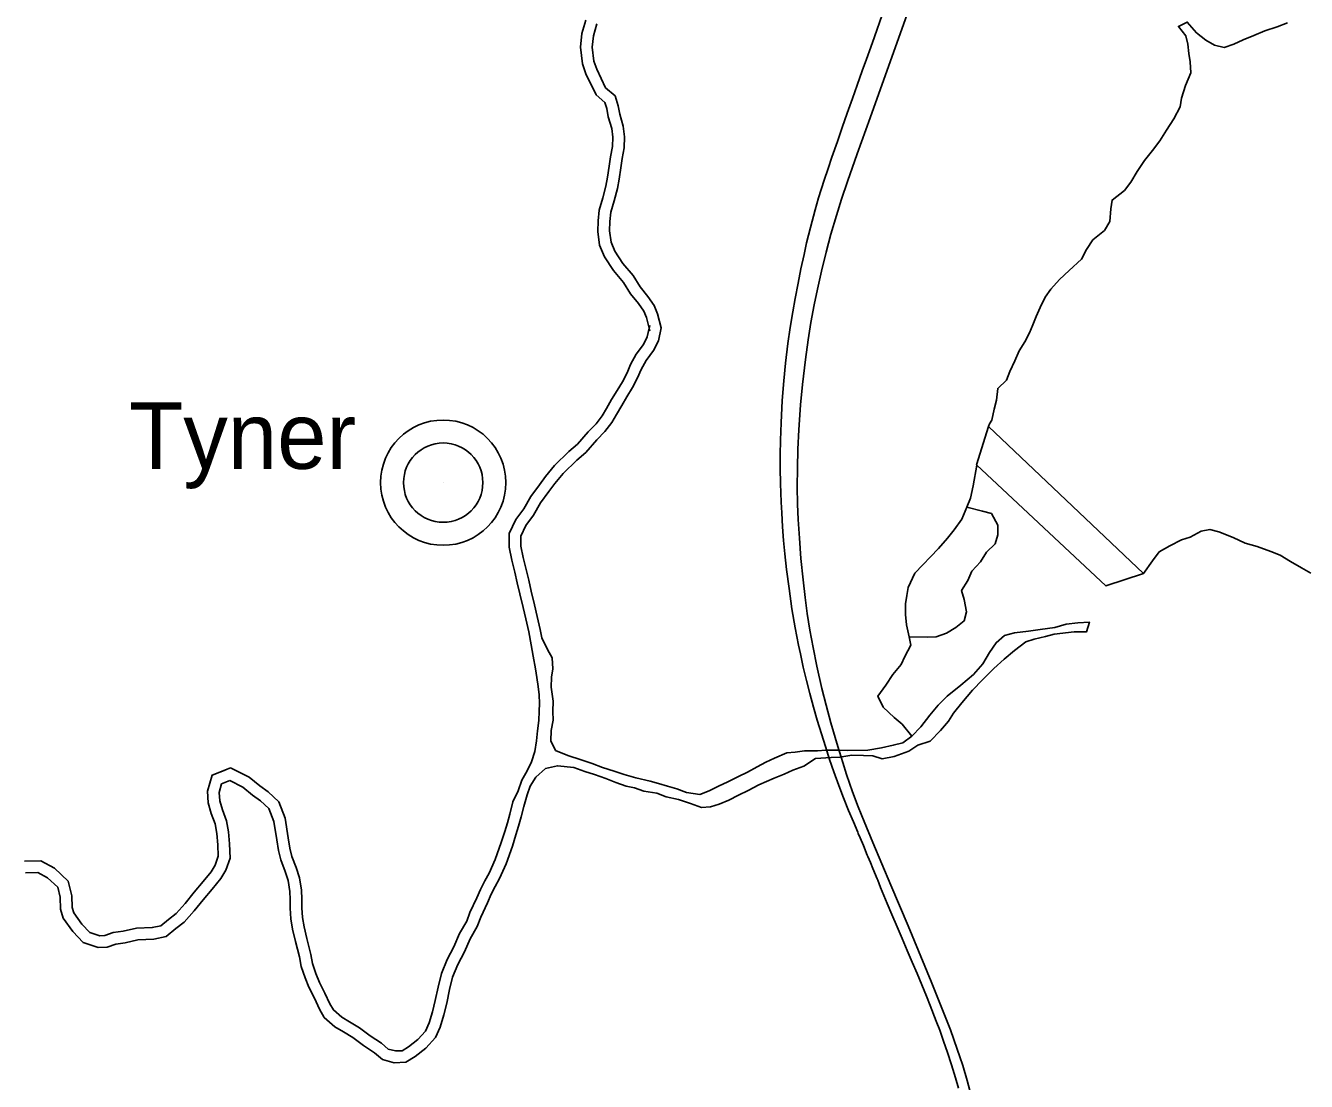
# Model space of a CAD drawing. Extents: x -12.1 to 34, y 0 to 22.
# Drawn here: x 8.417 to 9.844, y 14.694 to 15.871 of the extents above; entities that cross this region are included whole.
import ezdxf

# ---------------------------------------------------------------- set-up
doc = ezdxf.new("R2010")
doc.units = 0
for name, color, linetype in [('GM_X_Interstate_Route', 7, 'Continuous'), ('GM_X_Major_Lake', 7, 'Continuous'), ('GM_X_Major_River', 7, 'Continuous'), ('GM_X_Unincorporated', 7, 'Continuous'), ('GM_X_Unincorporated_Location', 7, 'Continuous'), ('GM_X_Unincorporated_Text', 7, 'Continuous')]:
    doc.layers.add(name, color=color, linetype=linetype)

msp = doc.modelspace()

# ---------------------------------------------------------------- linework, layer by layer
at = {"layer": 'GM_X_Interstate_Route'}
for points in [[(9.4582, 14.7214), (9.4553, 14.73), (9.4476, 14.7514), (9.4382, 14.7758), (9.4262, 14.8055), (9.4005, 14.8673), (9.3812, 14.9129), (9.3613, 14.9605), (9.3515, 14.9838), (9.345, 15), (9.3387, 15.0169), (9.3319, 15.0362), (9.3276, 15.0495), (9.3221, 15.0673), (9.3145, 15.0937), (9.3092, 15.1133), (9.3045, 15.132), (9.2989, 15.157), (9.2947, 15.1776), (9.2911, 15.1971), (9.2881, 15.2155), (9.2857, 15.2334), (9.2834, 15.2531), (9.2811, 15.2769), (9.2793, 15.2996), (9.2781, 15.3205), (9.2774, 15.3374), (9.277, 15.3567), (9.2771, 15.3776), (9.2776, 15.3986), (9.2786, 15.4202), (9.2806, 15.4481), (9.2827, 15.4707), (9.286, 15.4985), (9.289, 15.5205), (9.2922, 15.54), (9.2957, 15.5595), (9.2994, 15.5772), (9.3039, 15.5971), (9.3091, 15.6181), (9.3145, 15.6383), (9.3206, 15.659), (9.3264, 15.6774), (9.3331, 15.6972), (9.3439, 15.728), (9.3581, 15.7681), (9.4368, 15.9891)], [(9.4566, 14.6867), (9.4533, 14.6979), (9.4489, 14.7124), (9.4444, 14.7263), (9.4401, 14.739), (9.4358, 14.7511), (9.4319, 14.7614), (9.4252, 14.7788), (9.421, 14.7891), (9.4156, 14.8019), (9.4104, 14.8143), (9.4049, 14.8271), (9.3996, 14.84), (9.3939, 14.8534), (9.3884, 14.8663), (9.3825, 14.8802), (9.3773, 14.8925), (9.3717, 14.9059), (9.3699, 14.9102), (9.3666, 14.9183), (9.366, 14.9199), (9.3612, 14.9312), (9.3584, 14.9382), (9.3557, 14.9446), (9.3553, 14.9456), (9.355, 14.9462), (9.3506, 14.957), (9.347, 14.9656), (9.345, 14.9704), (9.3443, 14.972), (9.3395, 14.9833), (9.3342, 14.9962), (9.3285, 15.0102), (9.3232, 15.0237), (9.3177, 15.039), (9.313, 15.0528), (9.3083, 15.0672), (9.3038, 15.0816), (9.2992, 15.0967), (9.295, 15.1112), (9.2908, 15.1264), (9.2871, 15.141), (9.2836, 15.1557), (9.2804, 15.1705), (9.2784, 15.1802), (9.2747, 15.1996), (9.271, 15.2209), (9.2678, 15.2433), (9.2651, 15.2647), (9.2632, 15.2821), (9.2618, 15.2971), (9.2606, 15.3122), (9.2596, 15.3279), (9.2589, 15.3395), (9.2581, 15.3604), (9.2578, 15.3773), (9.2579, 15.3924), (9.2581, 15.4087), (9.2589, 15.4279), (9.2603, 15.4529), (9.262, 15.475), (9.2639, 15.4946), (9.2666, 15.5166), (9.2692, 15.5345), (9.272, 15.5517), (9.2746, 15.5666), (9.2778, 15.5838), (9.281, 15.5997), (9.2845, 15.6157), (9.2874, 15.6287), (9.2916, 15.6457), (9.2968, 15.6654), (9.3007, 15.6788), (9.307, 15.6987), (9.3113, 15.7114), (9.3156, 15.7241), (9.3217, 15.7417), (9.3271, 15.7571), (9.3326, 15.7731), (9.3384, 15.7896), (9.3437, 15.8044), (9.3494, 15.8203), (9.3541, 15.8334), (9.3588, 15.8466), (9.3629, 15.8581), (9.3717, 15.8828)], [(9.4709, 14.6783), (9.4663, 14.6951), (9.4613, 14.7118), (9.4582, 14.7214)]]:
    msp.add_lwpolyline(points, dxfattribs=at)
at = {"layer": 'GM_X_Major_Lake'}
msp.add_line((9.4899, 15.4241), (9.6629, 15.2602), dxfattribs=at)
for points in [[(9.8232, 15.8739), (9.8118, 15.8696), (9.7981, 15.8648), (9.7857, 15.8598), (9.774, 15.8551), (9.7634, 15.85), (9.7528, 15.8464), (9.7418, 15.8491), (9.7322, 15.8547), (9.7219, 15.8628), (9.7115, 15.8748), (9.7017, 15.8698), (9.7099, 15.8595), (9.7121, 15.85), (9.7135, 15.8397), (9.7147, 15.8304), (9.7155, 15.818), (9.7095, 15.8041), (9.705, 15.7899), (9.7037, 15.7803), (9.6967, 15.7667), (9.6883, 15.7542), (9.6809, 15.7424), (9.6728, 15.7317), (9.664, 15.7206), (9.6556, 15.7081), (9.6486, 15.6964), (9.6416, 15.6871), (9.6278, 15.6763), (9.6265, 15.6667), (9.6252, 15.6525), (9.6192, 15.6425), (9.6065, 15.6321), (9.5992, 15.6214), (9.5936, 15.6103), (9.5798, 15.5978), (9.5693, 15.5878), (9.5594, 15.577), (9.5531, 15.5681), (9.5475, 15.5567), (9.5433, 15.5467), (9.5395, 15.5374), (9.5357, 15.5285), (9.5304, 15.5185), (9.5244, 15.5082), (9.5196, 15.4971), (9.514, 15.4854), (9.5101, 15.4757), (9.5003, 15.4664), (9.499, 15.4533), (9.4965, 15.4433), (9.4938, 15.4309), (9.4913, 15.4269), (9.4899, 15.4241)], [(9.6629, 15.2602), (9.4899, 15.4241), (9.4913, 15.4269), (9.4938, 15.4309), (9.4965, 15.4433), (9.499, 15.4533), (9.5003, 15.4664), (9.5101, 15.4757), (9.514, 15.4854), (9.5196, 15.4971), (9.5244, 15.5082), (9.5304, 15.5185), (9.5357, 15.5285), (9.5395, 15.5374), (9.5433, 15.5467), (9.5475, 15.5567), (9.5531, 15.5681), (9.5594, 15.577), (9.5693, 15.5878), (9.5798, 15.5978), (9.5936, 15.6103), (9.5992, 15.6214), (9.6065, 15.6321), (9.6192, 15.6425), (9.6252, 15.6525), (9.6265, 15.6667), (9.6278, 15.6763), (9.6416, 15.6871), (9.6486, 15.6964), (9.6556, 15.7081), (9.664, 15.7206), (9.6728, 15.7317), (9.6809, 15.7424), (9.6883, 15.7542), (9.6967, 15.7667), (9.7037, 15.7803), (9.705, 15.7899), (9.7095, 15.8041), (9.7155, 15.818), (9.7147, 15.8304), (9.7135, 15.8397), (9.7121, 15.85), (9.7099, 15.8595), (9.7017, 15.8698), (9.7115, 15.8748), (9.7219, 15.8628), (9.7322, 15.8547), (9.7418, 15.8491), (9.7528, 15.8464), (9.7634, 15.85), (9.774, 15.8551), (9.7857, 15.8598), (9.7981, 15.8648), (9.8118, 15.8696), (9.8232, 15.8739)], [(9.6629, 15.2602), (9.6727, 15.2741), (9.6801, 15.2842), (9.6921, 15.291), (9.7051, 15.2975), (9.7147, 15.3008), (9.727, 15.3072), (9.7366, 15.3091), (9.7469, 15.3067), (9.7629, 15.3001), (9.776, 15.2938), (9.7895, 15.2903), (9.8048, 15.2847), (9.8151, 15.2806), (9.8265, 15.2735), (9.8389, 15.2665), (9.8492, 15.2606)]]:
    msp.add_lwpolyline(points, dxfattribs=at)
at = {"layer": 'GM_X_Major_River'}
for p, q in [((9.4899, 15.4241), (9.4768, 15.3813)), ((9.6629, 15.2602), (9.4899, 15.4241)), ((9.4768, 15.3813), (9.6208, 15.2464)), ((9.6208, 15.2464), (9.6629, 15.2602))]:
    msp.add_line(p, q, dxfattribs=at)
for points in [[(9.1127, 15.5306), (9.1089, 15.5453), (9.1058, 15.5527), (9.1001, 15.5611), (9.0913, 15.5719), (9.0835, 15.5845), (9.0722, 15.5978), (9.0622, 15.6132), (9.0567, 15.6259), (9.0548, 15.6415), (9.0552, 15.6532), (9.0563, 15.6652), (9.0604, 15.679), (9.0637, 15.6919), (9.0656, 15.7018), (9.0673, 15.7141), (9.069, 15.7246), (9.071, 15.736), (9.0715, 15.7465), (9.0703, 15.756), (9.0664, 15.7691), (9.0646, 15.7783), (9.0626, 15.785), (9.0527, 15.7935), (9.0415, 15.8171), (9.0376, 15.8283), (9.0353, 15.8468), (9.037, 15.8618), (9.0412, 15.877)], [(9.0412, 15.877), (9.037, 15.8618), (9.0353, 15.8468), (9.0376, 15.8283), (9.0415, 15.8171), (9.0527, 15.7935), (9.0626, 15.785), (9.0646, 15.7783), (9.0664, 15.7691), (9.0703, 15.756), (9.0715, 15.7465), (9.071, 15.736), (9.069, 15.7246), (9.0673, 15.7141), (9.0656, 15.7018), (9.0637, 15.6919), (9.0604, 15.679), (9.0563, 15.6652), (9.0552, 15.6532), (9.0548, 15.6415), (9.0567, 15.6259), (9.0622, 15.6132), (9.0722, 15.5978), (9.0835, 15.5845), (9.0913, 15.5719), (9.1001, 15.5611), (9.1058, 15.5527), (9.1089, 15.5453), (9.1119, 15.5336)], [(9.1253, 15.5338), (9.1213, 15.5494), (9.1174, 15.559), (9.1106, 15.5689), (9.102, 15.5795), (9.0941, 15.5922), (9.0827, 15.6056), (9.0737, 15.6194), (9.0694, 15.6293), (9.0679, 15.6421), (9.0682, 15.6524), (9.0692, 15.6627), (9.073, 15.6755), (9.0765, 15.6891), (9.0785, 15.6997), (9.0802, 15.7122), (9.0819, 15.7225), (9.084, 15.7346), (9.0846, 15.747), (9.0831, 15.7587), (9.0791, 15.7722), (9.0773, 15.7814), (9.074, 15.7924), (9.0633, 15.8016), (9.0536, 15.8221), (9.0504, 15.8313), (9.0485, 15.8469), (9.0498, 15.8594), (9.0536, 15.8729)], [(9.1119, 15.5336), (9.1098, 15.524), (9.1055, 15.5154), (9.0976, 15.5045), (9.0912, 15.4932), (9.0873, 15.4838), (9.0822, 15.4739), (9.0761, 15.464), (9.07, 15.4542), (9.0644, 15.4441), (9.0595, 15.4359), (9.0528, 15.4268), (9.044, 15.4179), (9.032, 15.4043), (9.0225, 15.396), (9.0066, 15.3806), (8.9965, 15.3684), (8.9896, 15.3591), (8.98, 15.3459), (8.9723, 15.3324), (8.9632, 15.3203), (8.9558, 15.3046), (8.9559, 15.2894), (8.9588, 15.2751), (8.9621, 15.2617), (8.965, 15.2498), (8.9679, 15.2374), (8.9716, 15.2222), (8.9745, 15.2095), (8.9777, 15.1951), (8.9806, 15.1805), (8.9828, 15.1679), (8.9853, 15.1538), (8.9868, 15.1441), (8.9882, 15.1344), (8.9893, 15.1248), (8.9897, 15.1151), (8.9894, 15.1069), (8.9888, 15.0964), (8.9875, 15.0848), (8.9865, 15.0738), (8.9844, 15.0617), (8.9807, 15.0502), (8.9761, 15.0404), (8.9702, 15.0299), (8.9658, 15.0181), (8.96, 15.0057), (8.9566, 14.992), (8.9539, 14.9822), (8.9509, 14.9728), (8.9471, 14.9604), (8.9404, 14.9413), (8.9335, 14.9263), (8.9288, 14.9176), (8.9239, 14.908), (8.92, 14.8986), (8.9122, 14.8824), (8.9086, 14.8725), (8.9007, 14.8589), (8.8943, 14.844), (8.8869, 14.8301), (8.8804, 14.8143), (8.8766, 14.7992), (8.8735, 14.7842), (8.8706, 14.7717), (8.8668, 14.7593), (8.8627, 14.7501), (8.8543, 14.7407), (8.8438, 14.7326), (8.8368, 14.7283), (8.8294, 14.728), (8.821, 14.7302), (8.8137, 14.7366), (8.8009, 14.7449), (8.789, 14.7538), (8.778, 14.7605), (8.7694, 14.7656), (8.76, 14.7738), (8.7562, 14.7806), (8.7506, 14.7924), (8.7447, 14.8045), (8.7406, 14.8143), (8.7368, 14.8254), (8.735, 14.8355), (8.7305, 14.8533), (8.7274, 14.8662), (8.7257, 14.8768), (8.725, 14.8875), (8.7249, 14.8973), (8.7245, 14.9072), (8.7224, 14.9209), (8.7187, 14.9326), (8.7138, 14.9449), (8.7116, 14.9541), (8.7098, 14.9654), (8.7063, 14.9873), (8.6993, 15.0055), (8.6872, 15.017), (8.6779, 15.0236), (8.6661, 15.033), (8.6455, 15.0437)], [(8.6507, 15.0409), (8.6661, 15.033), (8.6779, 15.0236), (8.6872, 15.017), (8.6993, 15.0055), (8.7063, 14.9873), (8.7098, 14.9654), (8.7116, 14.9541), (8.7138, 14.9449), (8.7187, 14.9326), (8.7224, 14.9209), (8.7245, 14.9072), (8.7249, 14.8973), (8.725, 14.8875), (8.7257, 14.8768), (8.7274, 14.8662), (8.7305, 14.8533), (8.735, 14.8355), (8.7368, 14.8254), (8.7406, 14.8143), (8.7447, 14.8045), (8.7506, 14.7924), (8.7562, 14.7806), (8.76, 14.7738), (8.7694, 14.7656), (8.778, 14.7605), (8.789, 14.7538), (8.8009, 14.7449), (8.8137, 14.7366), (8.821, 14.7302), (8.8294, 14.728), (8.8368, 14.7283), (8.8438, 14.7326), (8.8543, 14.7407), (8.8627, 14.7501), (8.8668, 14.7593), (8.8706, 14.7717), (8.8735, 14.7842), (8.8766, 14.7992), (8.8804, 14.8143), (8.8869, 14.8301), (8.8943, 14.844), (8.9007, 14.8589), (8.9086, 14.8725), (8.9122, 14.8824), (8.92, 14.8986), (8.9239, 14.908), (8.9288, 14.9176), (8.9335, 14.9263), (8.9404, 14.9413), (8.9471, 14.9604), (8.9509, 14.9728), (8.9539, 14.9822), (8.9566, 14.992), (8.96, 15.0057), (8.9658, 15.0181), (8.9702, 15.0299), (8.9761, 15.0404), (8.9807, 15.0502), (8.9844, 15.0617), (8.9865, 15.0738), (8.9875, 15.0848), (8.9888, 15.0964), (8.9894, 15.1069), (8.9897, 15.1151), (8.9893, 15.1248), (8.9882, 15.1344), (8.9868, 15.1441), (8.9853, 15.1538), (8.9828, 15.1679), (8.9806, 15.1805), (8.9777, 15.1951), (8.9745, 15.2095), (8.9716, 15.2222), (8.9679, 15.2374), (8.965, 15.2498), (8.9621, 15.2617), (8.9588, 15.2751), (8.9559, 15.2894), (8.9558, 15.3046), (8.9632, 15.3203), (8.9723, 15.3324), (8.98, 15.3459), (8.9896, 15.3591), (8.9965, 15.3684), (9.0066, 15.3806), (9.0225, 15.396), (9.032, 15.4043), (9.044, 15.4179), (9.0528, 15.4268), (9.0595, 15.4359), (9.0644, 15.4441), (9.07, 15.4542), (9.0761, 15.464), (9.0822, 15.4739), (9.0873, 15.4838), (9.0912, 15.4932), (9.0976, 15.5045), (9.1055, 15.5154), (9.1098, 15.524), (9.1126, 15.5366)], [(8.9923, 15.1886), (8.9905, 15.1978), (8.9872, 15.2124), (8.9843, 15.2251), (8.9806, 15.2404), (8.9777, 15.2528), (8.9748, 15.2648), (8.9715, 15.278), (8.9689, 15.2907), (8.9689, 15.3017), (8.9745, 15.3135), (8.9832, 15.3253), (8.9909, 15.3389), (9.0001, 15.3514), (9.0067, 15.3603), (9.0162, 15.3717), (9.0314, 15.3864), (9.0412, 15.395), (9.0535, 15.409), (9.0627, 15.4183), (9.0704, 15.4286), (9.0757, 15.4375), (9.0813, 15.4475), (9.0872, 15.4572), (9.0935, 15.4675), (9.0991, 15.4782), (9.103, 15.4875), (9.1086, 15.4975), (9.1167, 15.5086), (9.1222, 15.5196), (9.1253, 15.5338)], [(9.4899, 15.4241), (9.6629, 15.2602), (9.6208, 15.2464), (9.4768, 15.3813), (9.4899, 15.4241)], [(9.4772, 15.381), (9.473, 15.3579), (9.4699, 15.3443), (9.4661, 15.334), (9.4605, 15.3208), (9.4517, 15.3087), (9.4444, 15.2994), (9.4345, 15.2879), (9.4078, 15.2607), (9.4004, 15.2447), (9.3991, 15.2358), (9.3977, 15.2265), (9.3975, 15.2145), (9.3986, 15.2031), (9.4015, 15.1896), (9.4037, 15.1804), (9.3967, 15.1676), (9.3929, 15.1587), (9.3834, 15.1476), (9.3757, 15.1358), (9.3669, 15.1236), (9.3726, 15.1113), (9.3848, 15.0996), (9.394, 15.0922), (9.4047, 15.0788)], [(9.4661, 15.334), (9.4605, 15.3208), (9.4517, 15.3087), (9.4444, 15.2994), (9.4345, 15.2879), (9.4078, 15.2607), (9.4004, 15.2447), (9.3991, 15.2358), (9.3977, 15.2265), (9.3975, 15.2145), (9.3986, 15.2031), (9.4015, 15.1896)], [(9.4015, 15.1896), (9.4221, 15.1891), (9.4316, 15.1895), (9.4433, 15.1935), (9.4535, 15.2), (9.463, 15.2075), (9.4655, 15.2175), (9.4629, 15.231), (9.46, 15.2412), (9.467, 15.2523), (9.4715, 15.2626), (9.481, 15.273), (9.4877, 15.2841), (9.4975, 15.2934), (9.5003, 15.3034), (9.5006, 15.314), (9.4934, 15.3271), (9.4835, 15.3295), (9.4661, 15.334)], [(8.9721, 15.0004), (8.9761, 15.0134), (8.9792, 15.023), (8.9856, 15.0333), (8.9965, 15.043), (9.0096, 15.0459), (9.028, 15.0439), (9.0404, 15.0394), (9.0511, 15.0363), (9.0635, 15.0318), (9.0749, 15.0272), (9.0862, 15.0231), (9.0955, 15.0214), (9.1061, 15.0175), (9.1203, 15.0152), (9.131, 15.0113), (9.1445, 15.0082), (9.1579, 15.0037), (9.1704, 14.9992), (9.1803, 15), (9.1898, 15.0029), (9.2008, 15.0076), (9.2114, 15.013), (9.2223, 15.0184), (9.2343, 15.0246), (9.2513, 15.0322), (9.2622, 15.0365), (9.2721, 15.0408), (9.2842, 15.0456), (9.2972, 15.0538), (9.3146, 15.055), (9.3245, 15.0555), (9.3379, 15.0577), (9.3507, 15.0574), (9.361, 15.0568), (9.3716, 15.0537), (9.3851, 15.0563), (9.4013, 15.0621), (9.4115, 15.0689), (9.425, 15.0733), (9.4366, 15.0851), (9.4454, 15.0955), (9.451, 15.1044), (9.4605, 15.1162), (9.4721, 15.1301), (9.4833, 15.1416), (9.496, 15.1541), (9.5076, 15.1645), (9.5189, 15.1742), (9.5316, 15.1839), (9.5411, 15.1868), (9.5535, 15.1901), (9.5634, 15.1927), (9.5857, 15.1953), (9.5992, 15.1951), (9.6026, 15.2061), (9.5895, 15.2053), (9.5768, 15.2038), (9.5641, 15.2001), (9.5478, 15.1979), (9.5347, 15.196), (9.5191, 15.1941), (9.5078, 15.1912), (9.4986, 15.1829), (9.4913, 15.1722), (9.4839, 15.1594), (9.4734, 15.1476), (9.4593, 15.1357), (9.4441, 15.1235), (9.4339, 15.1135), (9.4248, 15.1024), (9.4146, 15.0892), (9.4047, 15.0788), (9.3945, 15.0716), (9.3839, 15.0687), (9.3708, 15.0658), (9.3556, 15.0632), (9.3326, 15.063), (9.323, 15.0633), (9.3088, 15.0631), (9.2996, 15.0627), (9.2851, 15.0626), (9.2748, 15.0611), (9.2653, 15.0603), (9.2515, 15.0542), (9.242, 15.0498), (9.2321, 15.0448), (9.2215, 15.0387), (9.2116, 15.034), (9.1996, 15.0278), (9.189, 15.0231), (9.1788, 15.0181), (9.1685, 15.0138), (9.1536, 15.0161), (9.1426, 15.0203), (9.1323, 15.0231), (9.1224, 15.0262), (9.1131, 15.0286), (9.0972, 15.0324), (9.084, 15.0362), (9.073, 15.0397)], [(8.9721, 15.0004), (8.9761, 15.0134), (8.9792, 15.023), (8.9856, 15.0333), (8.9965, 15.043), (9.0096, 15.0459), (9.028, 15.0439), (9.0404, 15.0394), (9.0511, 15.0363), (9.0635, 15.0318), (9.0749, 15.0272), (9.0862, 15.0231), (9.0955, 15.0214), (9.1061, 15.0175), (9.1203, 15.0152), (9.131, 15.0113), (9.1445, 15.0082), (9.1579, 15.0037), (9.1704, 14.9992), (9.1803, 15), (9.1898, 15.0029), (9.2008, 15.0076), (9.2114, 15.013), (9.2223, 15.0184), (9.2343, 15.0246), (9.2513, 15.0322), (9.2622, 15.0365), (9.2721, 15.0408), (9.2842, 15.0456), (9.2972, 15.0538), (9.3146, 15.055), (9.3245, 15.0555), (9.3379, 15.0577), (9.3507, 15.0574), (9.361, 15.0568), (9.3716, 15.0537), (9.3851, 15.0563), (9.4013, 15.0621), (9.4115, 15.0689), (9.425, 15.0733), (9.4366, 15.0851), (9.4454, 15.0955), (9.451, 15.1044), (9.4605, 15.1162), (9.4721, 15.1301), (9.4833, 15.1416), (9.496, 15.1541), (9.5076, 15.1645), (9.5189, 15.1742), (9.5316, 15.1839), (9.5411, 15.1868), (9.5535, 15.1901), (9.5634, 15.1927), (9.5857, 15.1953), (9.5992, 15.1951), (9.6026, 15.2061), (9.5895, 15.2053), (9.5768, 15.2038), (9.5641, 15.2001), (9.5478, 15.1979), (9.5347, 15.196), (9.5191, 15.1941), (9.5078, 15.1912), (9.4986, 15.1829), (9.4913, 15.1722), (9.4839, 15.1594), (9.4734, 15.1476), (9.4593, 15.1357), (9.4441, 15.1235), (9.4339, 15.1135), (9.4248, 15.1024), (9.4146, 15.0892), (9.4047, 15.0788)], [(9.073, 15.0397), (9.0599, 15.0438), (9.0485, 15.0484), (9.0361, 15.0525), (9.0212, 15.0574), (9.0077, 15.063), (9.0023, 15.0736), (9.0026, 15.085), (9.005, 15.0967), (9.0046, 15.1063), (9.0048, 15.1177), (9.0026, 15.1336), (9.0032, 15.1446), (9.0046, 15.1539), (9.0038, 15.166), (8.9988, 15.1755), (8.9923, 15.1886)], [(9.4047, 15.0788), (9.3945, 15.0716), (9.3839, 15.0687), (9.3708, 15.0658), (9.3556, 15.0632), (9.3326, 15.063), (9.323, 15.0633), (9.3088, 15.0631), (9.2996, 15.0627), (9.2851, 15.0626), (9.2748, 15.0611), (9.2653, 15.0603), (9.2515, 15.0542), (9.242, 15.0498), (9.2321, 15.0448), (9.2215, 15.0387), (9.2116, 15.034), (9.1996, 15.0278), (9.189, 15.0231), (9.1788, 15.0181), (9.1685, 15.0138), (9.1536, 15.0161), (9.1426, 15.0203), (9.1323, 15.0231), (9.1224, 15.0262), (9.1131, 15.0286), (9.0972, 15.0324), (9.084, 15.0362), (9.073, 15.0397)], [(8.6455, 15.0437), (8.6248, 15.0355), (8.6196, 15.0174), (8.6206, 15.0045), (8.624, 14.9926), (8.6281, 14.9812), (8.63, 14.9704), (8.6311, 14.9578), (8.6318, 14.945), (8.6282, 14.9351), (8.6238, 14.9277), (8.615, 14.9168), (8.6047, 14.9049), (8.595, 14.8925), (8.5848, 14.8812), (8.5764, 14.8746), (8.5678, 14.8676), (8.5581, 14.8655), (8.5405, 14.8647), (8.5257, 14.8616), (8.5145, 14.86), (8.5052, 14.8566), (8.4997, 14.8563), (8.4885, 14.8601), (8.4798, 14.8695), (8.4706, 14.8818), (8.4688, 14.8881), (8.4687, 14.9011), (8.4644, 14.9174), (8.4491, 14.9316), (8.4339, 14.9401), (8.4159, 14.9395)], [(8.4159, 14.9395), (8.4339, 14.9401), (8.4491, 14.9316), (8.4644, 14.9174), (8.4687, 14.9011), (8.4688, 14.8881), (8.4706, 14.8818), (8.4798, 14.8695), (8.4885, 14.8601), (8.4997, 14.8563), (8.5052, 14.8566), (8.5145, 14.86), (8.5257, 14.8616), (8.5405, 14.8647), (8.5581, 14.8655), (8.5678, 14.8676), (8.5764, 14.8746), (8.5848, 14.8812), (8.595, 14.8925), (8.6047, 14.9049), (8.615, 14.9168), (8.6238, 14.9277), (8.6282, 14.9351), (8.6318, 14.945), (8.6311, 14.9578), (8.63, 14.9704), (8.6281, 14.9812), (8.624, 14.9926), (8.6206, 15.0045), (8.6196, 15.0174), (8.6248, 15.0355), (8.64, 15.0415)], [(8.4169, 14.9264), (8.4307, 14.9269), (8.4414, 14.9209), (8.4528, 14.9104), (8.4557, 14.8994), (8.4558, 14.8862), (8.4587, 14.876), (8.4698, 14.8611), (8.4812, 14.8488), (8.4979, 14.8432), (8.5078, 14.8436), (8.5177, 14.8472), (8.528, 14.8487), (8.5421, 14.8517), (8.5598, 14.8525), (8.5736, 14.8555), (8.5845, 14.8644), (8.5937, 14.8716), (8.605, 14.8841), (8.6148, 14.8966), (8.625, 14.9084), (8.6345, 14.9202), (8.6401, 14.9295), (8.645, 14.943), (8.6441, 14.9587), (8.643, 14.9721), (8.6408, 14.9846), (8.6365, 14.9966), (8.6335, 15.0069), (8.6328, 15.0161), (8.6355, 15.0257), (8.6447, 15.0293)], [(8.6447, 15.0293), (8.659, 15.022), (8.67, 15.0132), (8.6789, 15.0069), (8.6882, 14.9981), (8.6936, 14.9839), (8.6969, 14.9633), (8.6988, 14.9516), (8.7013, 14.941), (8.7064, 14.9282), (8.7096, 14.9179), (8.7115, 14.9059), (8.7119, 14.897), (8.7119, 14.887), (8.7127, 14.8753), (8.7146, 14.8636), (8.7179, 14.8501), (8.7222, 14.8328), (8.7241, 14.8221), (8.7284, 14.8097), (8.7327, 14.7991), (8.7388, 14.7867), (8.7446, 14.7747), (8.7496, 14.7655), (8.7617, 14.7549), (8.7713, 14.7493), (8.7817, 14.743), (8.7934, 14.7342), (8.8059, 14.7261), (8.8148, 14.7184), (8.8279, 14.7149), (8.8407, 14.7154), (8.8512, 14.7218), (8.8632, 14.7312), (8.8738, 14.743), (8.879, 14.7547), (8.8832, 14.7682), (8.8863, 14.7814), (8.8894, 14.7964), (8.8928, 14.8102), (8.8987, 14.8245), (8.9061, 14.8384), (8.9124, 14.853), (8.9204, 14.8669), (8.9242, 14.8773), (8.9319, 14.8933), (8.9358, 14.9026), (8.9403, 14.9115), (8.9452, 14.9204), (8.9525, 14.9364), (8.9595, 14.9564), (8.9633, 14.9689), (8.9664, 14.9785), (8.9692, 14.9888), (8.9721, 15.0004)]]:
    msp.add_lwpolyline(points, dxfattribs=at)
at = {"layer": 'GM_X_Unincorporated'}
for radius in [0.0698, 0.0442]:
    msp.add_circle((8.8824, 15.3614), radius, dxfattribs=at)
at = {"layer": 'GM_X_Unincorporated_Location'}
msp.add_line((8.8824, 15.3614), (8.8824, 15.3614), dxfattribs=at)

# ---------------------------------------------------------------- texts
at = {"layer": 'GM_X_Unincorporated_Text'}
msp.add_text('Tyner', height=0.07404, rotation=0, dxfattribs=at).set_placement((8.5323, 15.3768))

doc.saveas('drawing.dxf')
